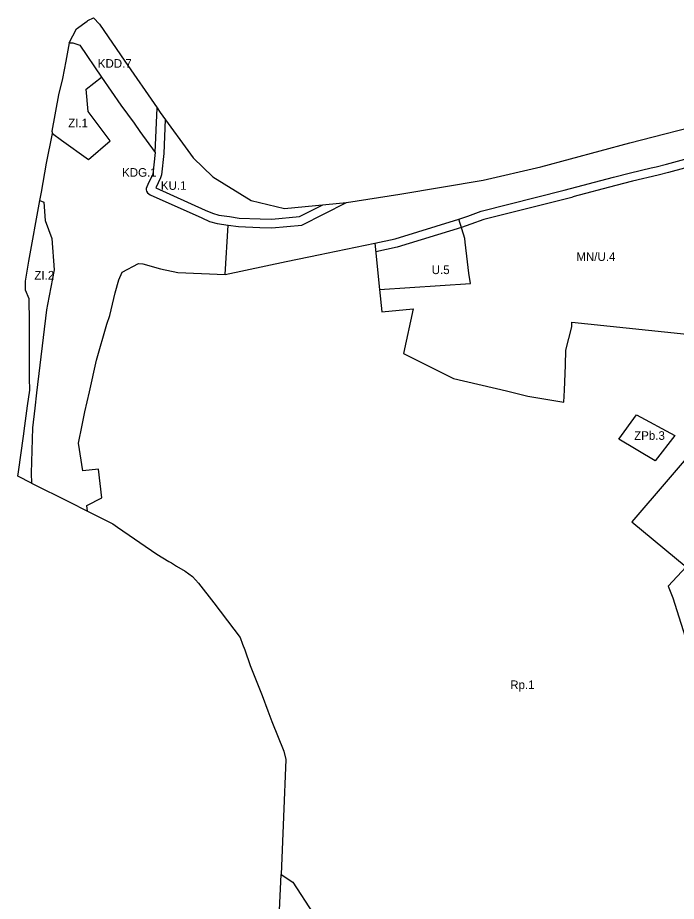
# Model space of a CAD drawing. Extents: x 7414808 to 7417449, y 5544732 to 5546764.
# Drawn here: x 7414808 to 7415190, y 5545373 to 5545886 of the extents above; entities that cross this region are included whole.
import ezdxf

# ---------------------------------------------------------------- set-up
doc = ezdxf.new("R2010")
doc.units = 0
for name, color, linetype in [('LIN_Linie Rozgraniczajace', 7, 'Continuous'), ('LIN_nieprzekraczale linie zabudowy', 7, 'Continuous'), ('TXT_Oznaczenia Przeznaczenia', 7, 'Continuous')]:
    doc.layers.add(name, color=color, linetype=linetype)

msp = doc.modelspace()

# ---------------------------------------------------------------- linework, layer by layer
at = {"layer": 'LIN_Linie Rozgraniczajace'}
msp.add_line((7414887.3, 5545807.83), (7414885.98, 5545795.31), dxfattribs=at)
for points in [[(7414837.31, 5545871.44), (7414841.65, 5545879.66), (7414847.83, 5545884.16), (7414848.26, 5545884.41), (7414851.57, 5545886.1), (7414854.97, 5545882.37), (7414869.73, 5545860.92), (7414888.49, 5545833.66)], [(7414837.31, 5545871.44), (7414835.53, 5545860.82), (7414833.51, 5545850.69), (7414831.26, 5545841.32), (7414827.38, 5545820.23), (7414827.71, 5545818.78)], [(7414837.31, 5545871.44), (7414839.47, 5545871.54), (7414842.47, 5545870.43), (7414843.51, 5545870.05), (7414856.19, 5545851.6)], [(7414827.71, 5545818.78), (7414832.93, 5545815.03), (7414848.59, 5545803.79), (7414861.18, 5545814.52), (7414848.38, 5545831.54), (7414847.23, 5545844.49), (7414856.19, 5545851.6)], [(7414856.19, 5545851.6), (7414867.41, 5545835.27), (7414875.03, 5545824.91), (7414878.49, 5545819.91), (7414887.3, 5545807.83)], [(7414998.29, 5545778.83), (7415029.23, 5545783.64), (7415077.77, 5545791.68), (7415111.05, 5545799.42), (7415162.88, 5545813.44), (7415210.97, 5545825.8), (7415265.57, 5545840.42), (7415307.77, 5545850.49)], [(7414887.3, 5545807.83), (7414888.49, 5545833.66)], [(7414888.49, 5545833.66), (7414890.28, 5545831.06), (7414909.35, 5545804.76), (7414920.84, 5545793.7), (7414943.1, 5545780), (7414962.35, 5545775.26), (7414998.29, 5545778.83)], [(7415076.55, 5545773.66), (7415124.61, 5545785.87), (7415153.38, 5545793.44), (7415163.14, 5545796.01), (7415175.24, 5545798.83), (7415178.09, 5545799.48), (7415184.02, 5545801.09), (7415216.01, 5545809.79), (7415224.92, 5545812.16), (7415234.97, 5545813.75), (7415239.08, 5545814.55), (7415239.39, 5545816.05), (7415287.07, 5545828.44)], [(7414820.27, 5545780.03), (7414821.4, 5545784.74), (7414824.19, 5545801.59), (7414827.71, 5545818.78)], [(7414885.98, 5545795.31), (7414883.07, 5545789.21), (7414882.44, 5545787.94), (7414882.14, 5545786.81), (7414882.14, 5545786.04), (7414882.32, 5545785.29), (7414882.76, 5545784.47), (7414884.47, 5545783.21), (7414914.34, 5545769.82), (7414918.83, 5545767.78), (7414923.21, 5545766.59), (7414929.7, 5545765.66)], [(7414815.61, 5545615.81), (7414807.51, 5545619.85), (7414807.89, 5545622.45), (7414810.83, 5545643.05), (7414811.7, 5545649.15), (7414813.25, 5545660.72), (7414814.54, 5545669.8), (7414814.43, 5545676.78), (7414814.43, 5545692.41), (7414814.29, 5545709.44), (7414814.15, 5545722.85), (7414812.08, 5545727.82), (7414811.96, 5545733.08), (7414813.95, 5545744.7), (7414820.27, 5545780.03)], [(7414820.27, 5545780.03), (7414822.66, 5545778.92), (7414823.41, 5545768.25), (7414827.32, 5545757.79), (7414828.76, 5545739.74), (7414824.89, 5545719.53), (7414824.31, 5545716.49), (7414818.41, 5545668.28), (7414817.42, 5545659.27), (7414816.05, 5545647.9), (7414815.33, 5545621.64), (7414815.61, 5545615.81)], [(7414929.7, 5545765.66), (7414935.6, 5545764.78), (7414948.03, 5545764.35), (7414955.11, 5545764.03), (7414972.44, 5545765.66), (7414998.29, 5545778.83)], [(7414986.74, 5545749.32), (7415014.81, 5545755.19), (7415026.54, 5545757.64), (7415063.6, 5545769.1), (7415068.79, 5545770.92), (7415076.55, 5545773.66)], [(7415017.48, 5545728.34), (7415070.23, 5545731.74), (7415069.41, 5545737.71), (7415068.55, 5545744.26), (7415067.31, 5545755.8), (7415066.95, 5545757.94), (7415063.6, 5545769.1)], [(7414928.01, 5545737.05), (7414929.7, 5545765.66)], [(7415014.81, 5545755.19), (7415017.48, 5545728.34), (7415018.77, 5545715.37), (7415036.99, 5545717.06), (7415031.47, 5545691.02), (7415049.17, 5545682.26), (7415060.5, 5545676.64), (7415091.25, 5545669.34), (7415103.65, 5545666.39), (7415124.44, 5545662.89), (7415124.9, 5545669.82), (7415125.43, 5545684.36), (7415125.59, 5545693.03), (7415129.16, 5545706.49), (7415129.15, 5545709.3), (7415227.47, 5545699.08), (7415227.26, 5545683.57), (7415251.41, 5545666.98), (7415264.96, 5545654.43)], [(7414928.01, 5545737.05), (7414963.34, 5545744.43), (7414983, 5545748.54), (7414986.74, 5545749.32)], [(7414847.96, 5545599.62), (7414847.66, 5545602.74), (7414856.43, 5545607.27), (7414854.5, 5545624.01), (7414845.32, 5545622.94), (7414842.79, 5545639.06), (7414844.87, 5545649.48), (7414846.43, 5545657.25), (7414849.16, 5545668.79), (7414853.25, 5545687.28), (7414859.25, 5545708.04), (7414861.09, 5545713.1), (7414864.04, 5545726.35), (7414866.14, 5545733.94), (7414868.08, 5545738.27), (7414877.66, 5545743.44), (7414880.06, 5545743.22), (7414890.4, 5545740.35), (7414900.43, 5545738.12), (7414928.01, 5545737.05)], [(7415195.41, 5545567.15), (7415185, 5545555.96), (7415187.67, 5545549.14), (7415197.25, 5545519.26), (7415200.72, 5545510.73), (7415204.22, 5545505.53), (7415207.83, 5545501.85), (7415232.02, 5545534.26), (7415246.98, 5545554.27), (7415257.15, 5545567.91), (7415261.16, 5545572.61), (7415272.98, 5545586.38), (7415276.77, 5545590.85), (7415287.06, 5545599.91), (7415290.13, 5545602.87), (7415293.17, 5545606.19), (7415296.17, 5545609.45), (7415301.08, 5545614.81), (7415304.27, 5545619.8), (7415311.8, 5545627.19), (7415315.56, 5545630.13), (7415326.03, 5545639.72), (7415348.73, 5545667.79)], [(7415229.23, 5545617.82), (7415218.68, 5545627.77), (7415204.94, 5545640.79), (7415204.93, 5545641.18), (7415163.9, 5545593.3), (7415195.41, 5545567.15)], [(7414815.61, 5545615.81), (7414837.32, 5545604.98), (7414847.96, 5545599.62)], [(7414847.96, 5545599.62), (7414862.75, 5545592.16), (7414865.42, 5545590.19), (7414888.26, 5545574.66), (7414895.3, 5545570.38), (7414896.7, 5545569.54), (7414899.77, 5545567.65), (7414904.73, 5545564.65), (7414908.99, 5545561.69), (7414912.54, 5545557.64), (7414921.35, 5545546.39), (7414932.87, 5545530.99), (7414936.64, 5545526.2), (7414937.98, 5545522.39), (7414939.29, 5545519.09), (7414942.51, 5545509.98), (7414949.32, 5545492.41), (7414952.61, 5545483.59), (7414955.05, 5545477.44), (7414961.94, 5545460.15), (7414963.15, 5545455.38), (7414961.76, 5545422.13), (7414960.34, 5545388.52)], [(7414951.29, 5545327.19), (7414951.66, 5545331.58), (7414956.97, 5545347.63), (7414958.95, 5545355.47), (7414960.34, 5545388.52)], [(7414960.34, 5545388.52), (7414967.23, 5545384.1), (7414979.04, 5545365.94), (7414986.08, 5545355.13), (7414999.04, 5545334.96), (7415021.31, 5545321.41), (7415031.52, 5545306.93), (7415035.18, 5545299.08), (7415041.54, 5545278.35), (7415045.93, 5545264.7), (7415046.82, 5545261.63), (7415052.56, 5545250.21), (7415070.23, 5545234.46)]]:
    msp.add_lwpolyline(points, dxfattribs=at)
msp.add_lwpolyline([(7415156.46, 5545641.35), (7415166.7, 5545655.52), (7415188.98, 5545643.54), (7415177.46, 5545628.77)], close=True, dxfattribs=at)
at = {"layer": 'LIN_nieprzekraczale linie zabudowy'}
msp.add_line((7414892.27, 5545807.3), (7414890.95, 5545794.79), dxfattribs=at)
for points in [[(7414893.19, 5545827.05), (7414892.27, 5545807.3), (7414890.95, 5545794.79), (7414890.49, 5545793.16), (7414887.67, 5545787.25), (7414916.4, 5545774.38), (7414920.53, 5545772.5), (7414924.22, 5545771.5), (7414930.41, 5545770.61), (7414936.06, 5545769.77), (7414948.23, 5545769.35), (7414954.99, 5545769.04), (7414971.02, 5545770.55), (7414984.61, 5545777.47)], [(7415217.31, 5545804.96), (7415185.33, 5545796.26), (7415179.31, 5545794.63), (7415164.34, 5545791.16), (7415154.65, 5545788.6), (7415129.81, 5545782.07), (7415129.83, 5545781.81), (7415077.99, 5545768.86), (7415070.45, 5545766.2), (7415065.17, 5545764.35), (7415027.79, 5545752.79), (7415015.31, 5545750.18)]]:
    msp.add_lwpolyline(points, dxfattribs=at)

# ---------------------------------------------------------------- texts
at = {"layer": 'TXT_Oznaczenia Przeznaczenia'}
for s, p in [('KDD.7', (7414854.01, 5545857.02)), ('ZI.1', (7414836.8, 5545822.41)), ('KDG.1', (7414868.1, 5545793.74)), ('KU.1', (7414890.62, 5545786.15)), ('MN/U.4', (7415131.76, 5545744.86)), ('U.5', (7415047.82, 5545737.21)), ('ZI.2', (7414817.21, 5545734.04)), ('ZPb.3', (7415165.3, 5545640.96)), ('Rp.1', (7415093.39, 5545496.23))]:
    msp.add_text(s, height=5, dxfattribs=at).set_placement(p)

doc.saveas('drawing.dxf')
